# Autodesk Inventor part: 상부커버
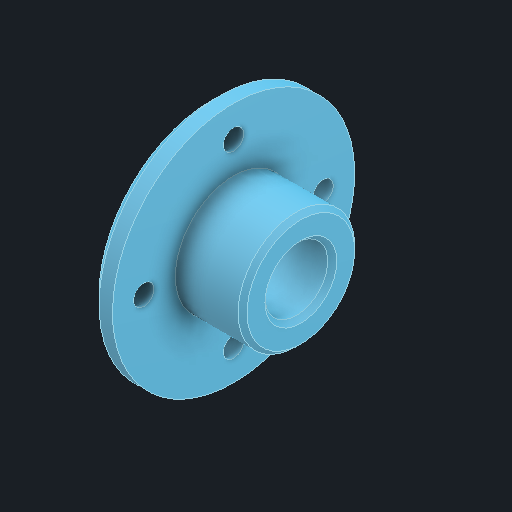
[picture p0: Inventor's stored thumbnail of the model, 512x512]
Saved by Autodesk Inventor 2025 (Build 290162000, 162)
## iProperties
Created: 2025-08
Part Number: 상부커버
Material: 알루미늄 6061
Document SubType Name: Modeling
Designer: infra15
Density: 2.71 g/cm^3
Appearance: 기본값
Author: jhkim
Sending System: Autodesk Inventor 2026
Preprocessor: ST-DEVELOPER v20.1
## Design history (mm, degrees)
feature "솔리드1"
node "솔리드2"
